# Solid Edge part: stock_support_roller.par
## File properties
Title: Stock support roller
Author: Abhinav Rai
Template: Normal.par
Last saved by: Cadcim
Revision: 10
Application: Solid Edge
Material: aluminum
Accuracy: 0.99
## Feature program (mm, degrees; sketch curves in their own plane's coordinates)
sketch for "unnamed RevolvedProtrusion 1" plane through (0, 0, 0) normal (0, -1, 0) x-axis (1, 0, 0)
  line (60, 0) -> (60, 18.669)
  line (60, 18.669) -> (15.55, 18.669)
  line (15.55, 18.669) -> (15.55, 92.075)
  line (15.55, 92.075) -> (-2.2388, 92.075)
  line (-2.2388, 92.075) -> (-111.45, 29.0219)
  line (-220.6612, 92.075) -> (-111.45, 29.0219)
  line (-238.45, 92.075) -> (-220.6612, 92.075)
  line (-238.45, 18.669) -> (-238.45, 92.075)
  line (-282.9, 18.669) -> (-238.45, 18.669)
  line (-282.9, 0) -> (-282.9, 18.669)
revolve "unnamed RevolvedProtrusion 1" add full turn 360 deg about sketch line (-282.9, 0) -> (60, 0)
chamfer "unnamed Chamfer 1"
fillet "Round_1" radius 1.5748
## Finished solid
Body 1: solid body, 14 faces, 13 edges, 0 vertices.
  Faces by surface: cone 4, cylinder 4, plane 4, torus 2
  Edges by curve: circle 13
Bounding box of the edges (mm; curved faces can reach further): 342.900 x 184.150 x 184.150, from (-282.9, -92.075, -92.075) to (60, 92.075, 92.075).
Cylindrical faces by radius (mm): R18.669 x2, R92.075 x2
Conical faces (half-angle, radius in mm at the cone's reference point): 30 deg R29.0219 x1, 30 deg R92.075 x1, 45 deg R17.0942 x1, 45 deg R18.669 x1
Toroidal faces (ring radius, tube radius in mm): R20.2438 r1.5748 x2
Planar faces by outward normal: +x 2, -x 2
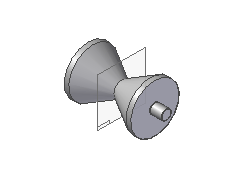
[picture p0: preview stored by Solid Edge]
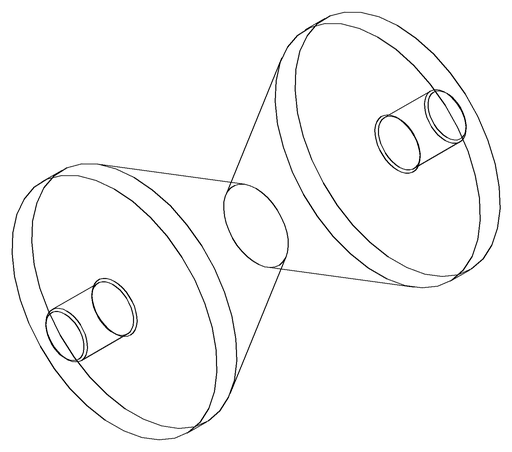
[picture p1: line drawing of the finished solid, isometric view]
